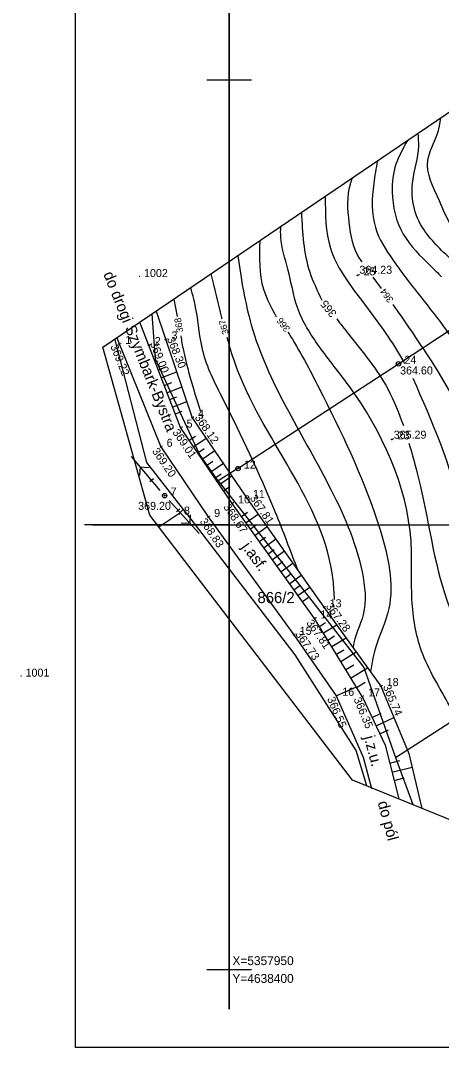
# Model space of a CAD drawing. Extents: x 4632591 to 4651936, y 5351032 to 5369988.
# Drawn here: x 4638376.6 to 4638423.8, y 5357941.2 to 5358056.7 of the extents above; entities that cross this region are included whole.
import ezdxf

# ---------------------------------------------------------------- set-up
doc = ezdxf.new("R2010")
doc.units = 0
for name, color, linetype in [('EBUPP_312', 7, 'Continuous'), ('EDZPD_211', 7, 'Continuous'), ('EDZPD_219', 7, 'Continuous'), ('EDZPP_202', 7, 'Continuous'), ('SDRPK_420', 7, 'Continuous'), ('SDRPK_432', 7, 'Continuous'), ('UEEPA_510', 7, 'Continuous'), ('UEETA_517', 7, 'Continuous'), ('Warstwa 25', 7, 'Continuous'), ('Warstwa 40', 7, 'Continuous'), ('Warstwa 60', 7, 'Continuous'), ('Warstwa 62', 7, 'Continuous'), ('WUKPS_403', 7, 'Continuous'), ('WUKPS_820', 7, 'Continuous'), ('WUKPS_824', 7, 'Continuous'), ('WWRPH_811', 7, 'Continuous'), ('WWRPH_812', 7, 'Continuous'), ('WWRPH_814', 7, 'Continuous')]:
    doc.layers.add(name, color=color, linetype=linetype)

msp = doc.modelspace()

# ---------------------------------------------------------------- linework, layer by layer
at = {"layer": 'EBUPP_312'}
msp.add_lwpolyline([(4638382.73, 5358114.56), (4638591.48, 5358114.56), (4638591.48, 5357941.24), (4638382.73, 5357941.24), (4638382.73, 5358114.56)], dxfattribs=at)
at = {"layer": 'EDZPD_219'}
for p, q in [((4638419.02, 5358018.09), (4638429.37, 5358024.9)), ((4638391.73, 5358018.61), (4638391.37, 5358023.66)), ((4638390.75, 5358007), (4638387.18, 5358020.8)), ((4638396.67, 5358007.92), (4638391.73, 5358018.61)), ((4638400.99, 5358006.31), (4638419.02, 5358018.09)), ((4638398.75, 5358004.93), (4638396.67, 5358007.92)), ((4638394.86, 5358001.71), (4638390.75, 5358007)), ((4638400.99, 5358006.31), (4638398.75, 5358004.93)), ((4638398.75, 5358004.93), (4638404.22, 5357997.93)), ((4638394.86, 5358001.71), (4638394.25, 5358001.14)), ((4638395.23, 5358001.26), (4638394.86, 5358001.71)), ((4638394.25, 5358001.14), (4638392.12, 5357999.73)), ((4638407.4, 5357985.38), (4638395.23, 5358001.26)), ((4638404.22, 5357997.93), (4638415.12, 5357983.94)), ((4638414.27, 5357974.64), (4638407.4, 5357985.38)), ((4638415.12, 5357983.94), (4638418.67, 5357973.84)), ((4638418.67, 5357973.84), (4638428.49, 5357980.16)), ((4638415.46, 5357970.64), (4638414.27, 5357974.64)), ((4638418.67, 5357973.84), (4638420.62, 5357968.54))]:
    msp.add_line(p, q, dxfattribs=at)
at = {"layer": 'EDZPP_202'}
for centre in [(4638419.02, 5358018.09), (4638400.99, 5358006.31)]:
    msp.add_circle(centre, 0.25, dxfattribs=at)
at = {"layer": 'SDRPK_420'}
msp.add_line((4638412.04, 5357980.77), (4638414.24, 5357981.75), dxfattribs=at)
for points in [[(4638414.94, 5357980.7), (4638409.59, 5357989.47), (4638400.34, 5358002.4), (4638394.55, 5358010.92), (4638389.98, 5358022.76)], [(4638387.39, 5358021), (4638392.31, 5358008.76), (4638397.65, 5358000.87), (4638407.26, 5357987.63), (4638412.04, 5357980.77)], [(4638412.04, 5357980.77), (4638415.06, 5357973.86), (4638416, 5357970.36)], [(4638414.94, 5357980.7), (4638417.53, 5357975.21), (4638419.05, 5357969.18)]]:
    msp.add_lwpolyline(points, dxfattribs=at)
at = {"layer": 'UEEPA_510'}
msp.add_circle((4638392.75, 5358003.27), 0.25, dxfattribs=at)
at = {"layer": 'UEETA_517'}
for p, q in [((4638392.27, 5358003.84), (4638389.04, 5358007.66)), ((4638390.01, 5358006.52), (4638389.92, 5358005.52)), ((4638390.01, 5358006.52), (4638391, 5358006.43)), ((4638391.49, 5358005.15), (4638391.11, 5358004.83)), ((4638393.26, 5358002.72), (4638396.63, 5357999.02)), ((4638394.08, 5358001.44), (4638394.45, 5358001.78)), ((4638395.61, 5358000.13), (4638395.66, 5358001.13)), ((4638395.61, 5358000.13), (4638394.62, 5358000.18))]:
    msp.add_line(p, q, dxfattribs=at)
at = {"layer": 'Warstwa 40'}
for p, q in [((4638385.83, 5358019.95), (4638506.88, 5358102.23)), ((4638391.08, 5358001.06), (4638385.83, 5358019.95)), ((4638413.84, 5357971.3), (4638391.08, 5358001.06)), ((4638432.85, 5357963.55), (4638413.84, 5357971.3))]:
    msp.add_line(p, q, dxfattribs=at)
at = {"layer": 'Warstwa 60'}
for p, q in [((4638400, 5358109.24), (4638400, 5358000)), ((4638400, 5358000), (4638400, 5358108.37)), ((4638397.5, 5358050), (4638400, 5358050)), ((4638400, 5358050), (4638402.5, 5358050)), ((4638400, 5358000), (4638383.76, 5358000)), ((4638384.64, 5358000), (4638400, 5358000)), ((4638400, 5357945.55), (4638400, 5358000)), ((4638400, 5358000), (4638400, 5357945.55)), ((4638400, 5358000), (4638516.95, 5358000)), ((4638397.5, 5357950), (4638400, 5357950)), ((4638400, 5357950), (4638402.5, 5357950))]:
    msp.add_line(p, q, dxfattribs=at)
at = {"layer": 'WUKPS_403'}
for centre in [(4638414.43, 5358028.03), (4638387.66, 5358020.32), (4638390.97, 5358020.19), (4638392.86, 5358020.83), (4638419.02, 5358018.09), (4638395.83, 5358012.03), (4638394.55, 5358010.92), (4638418.27, 5358009.59), (4638392.31, 5358008.76), (4638392.75, 5358003.27), (4638402, 5358003), (4638400.34, 5358002.4), (4638397.65, 5358000.87), (4638410.62, 5357990.72), (4638409.59, 5357989.47), (4638407.26, 5357987.63), (4638412.04, 5357980.77), (4638417.03, 5357981.86), (4638414.94, 5357980.7)]:
    msp.add_circle(centre, 0.045, dxfattribs=at)
at = {"layer": 'WUKPS_820'}
for p, q in [((4638392.05, 5358017.4), (4638392.92, 5358017.74)), ((4638394.1, 5358017.15), (4638392.4, 5358016.5)), ((4638392.72, 5358015.66), (4638393.55, 5358015.98)), ((4638394.67, 5358015.45), (4638393.04, 5358014.82)), ((4638393.34, 5358014.06), (4638394.14, 5358014.37)), ((4638395.22, 5358013.82), (4638393.66, 5358013.22)), ((4638393.96, 5358012.45), (4638394.72, 5358012.75)), ((4638395.52, 5358009.5), (4638396.21, 5358009.97)), ((4638397.42, 5358009.71), (4638396.02, 5358008.76)), ((4638396.48, 5358008.08), (4638397.18, 5358008.56)), ((4638398.38, 5358008.29), (4638396.98, 5358007.34)), ((4638397.45, 5358006.66), (4638398.15, 5358007.14)), ((4638399.35, 5358006.87), (4638397.95, 5358005.92)), ((4638398.41, 5358005.24), (4638399.11, 5358005.72)), ((4638400.32, 5358005.46), (4638398.91, 5358004.5)), ((4638399.38, 5358003.82), (4638400.08, 5358004.3)), ((4638401.39, 5358000.94), (4638402.08, 5358001.43)), ((4638403.28, 5358001.18), (4638401.91, 5358000.2)), ((4638402.39, 5357999.53), (4638403.07, 5358000.02)), ((4638404.27, 5357999.77), (4638402.91, 5357998.8)), ((4638403.39, 5357998.13), (4638404.07, 5357998.61)), ((4638405.26, 5357998.36), (4638403.92, 5357997.4)), ((4638404.4, 5357996.73), (4638405.07, 5357997.21)), ((4638406.21, 5357997.01), (4638404.88, 5357996.06)), ((4638405.36, 5357995.39), (4638406.02, 5357995.86)), ((4638407.15, 5357995.66), (4638405.84, 5357994.72)), ((4638406.32, 5357994.04), (4638406.97, 5357994.51)), ((4638408.1, 5357994.31), (4638406.8, 5357993.37)), ((4638407.28, 5357992.7), (4638407.93, 5357993.17)), ((4638409.05, 5357992.96), (4638407.76, 5357992.03)), ((4638408.24, 5357991.36), (4638408.88, 5357991.82)), ((4638410.14, 5357988.57), (4638410.84, 5357989.01)), ((4638412.08, 5357988.71), (4638410.61, 5357987.81)), ((4638411.07, 5357987.04), (4638411.84, 5357987.51)), ((4638413.14, 5357987.24), (4638411.54, 5357986.27)), ((4638412.05, 5357985.44), (4638412.88, 5357985.94)), ((4638414.28, 5357985.66), (4638412.56, 5357984.6)), ((4638413.1, 5357983.71), (4638414, 5357984.26)), ((4638415.56, 5357983.89), (4638413.69, 5357982.75)), ((4638414.32, 5357981.72), (4638415.29, 5357982.32)), ((4638416.06, 5357978.33), (4638417.08, 5357978.81)), ((4638416.51, 5357977.38), (4638418.51, 5357978.32)), ((4638416.92, 5357976.5), (4638417.91, 5357976.96)), ((4638418.04, 5357973.19), (4638419.18, 5357973.48)), ((4638418.29, 5357972.19), (4638420.56, 5357972.76)), ((4638418.53, 5357971.25), (4638419.65, 5357971.54))]:
    msp.add_line(p, q, dxfattribs=at)
at = {"layer": 'WUKPS_824'}
for points in [[(4638391.79, 5358024), (4638395.83, 5358012.03), (4638402, 5358003), (4638410.62, 5357990.72), (4638417.03, 5357981.86)], [(4638417.03, 5357981.86), (4638420.19, 5357974.3), (4638421.66, 5357968.11)]]:
    msp.add_lwpolyline(points, dxfattribs=at)
at = {"layer": 'WWRPH_811'}
for p, q in [((4638417.13, 5358026.55), (4638416.18, 5358027.83)), ((4638393.8, 5358025.37), (4638394.16, 5358023.4))]:
    msp.add_line(p, q, dxfattribs=at)
for points in [[(4638429.78, 5358029.1), (4638424.93, 5358033.66), (4638423.62, 5358036.41), (4638422.31, 5358040.97), (4638423.37, 5358043.85), (4638423.79, 5358045.75)], [(4638420.04, 5358043.2), (4638418.74, 5358040.53), (4638418.31, 5358037.41), (4638419.56, 5358032.66), (4638422.62, 5358029.09), (4638423.85, 5358027.88)], [(4638414.96, 5358029.5), (4638414.68, 5358029.9), (4638413.49, 5358033.97), (4638413.62, 5358038.28), (4638413.86, 5358039)], [(4638403.43, 5358031.91), (4638403.86, 5358026.47), (4638405.29, 5358023.38)], [(4638399.21, 5358023.11), (4638399.17, 5358023.28), (4638398, 5358028.22)], [(4638429.48, 5357998.93), (4638429.44, 5358001.08), (4638422.12, 5358019.34), (4638418.41, 5358024.77)], [(4638394.56, 5358021.23), (4638394.86, 5358019.59), (4638395.92, 5358015.52), (4638396.76, 5358012.77)], [(4638406.61, 5358021.64), (4638407.11, 5358020.84), (4638410.55, 5358014.46), (4638416.99, 5357999.33), (4638417.93, 5357990.58), (4638416.37, 5357985.89), (4638415.87, 5357983.47)], [(4638411.84, 5357991.59), (4638411.68, 5357993.76), (4638400.67, 5358018.15), (4638399.78, 5358021.03)]]:
    msp.add_spline(points, degree=3, dxfattribs=at)
at = {"layer": 'WWRPH_812'}
for points in [[(4638429.32, 5358024.94), (4638427.44, 5358027.34), (4638423.87, 5358030.84), (4638421.06, 5358034.72), (4638420.62, 5358038.6), (4638421.31, 5358042.54), (4638421.22, 5358044)], [(4638416.66, 5358040.9), (4638416.24, 5358038.35), (4638416.43, 5358033.41), (4638418.37, 5358029.78), (4638424, 5358022.4), (4638426.69, 5358017.96), (4638428.19, 5358012.08), (4638431.44, 5358002.21), (4638432.31, 5357998.45), (4638431.75, 5357994.2), (4638430.75, 5357990.45), (4638430.69, 5357987.76), (4638431.75, 5357984.32), (4638434.63, 5357979.63), (4638437.75, 5357976.69), (4638441.32, 5357974.51), (4638445.18, 5357971.85)], [(4638410.8, 5358036.92), (4638411.37, 5358031.09), (4638414.74, 5358025.4), (4638418.81, 5358019.65), (4638419.71, 5358018.14)], [(4638434.39, 5357964.59), (4638430.31, 5357968.13), (4638428.44, 5357971.44), (4638425, 5357979.2), (4638421.75, 5357985.45), (4638420.56, 5357991.2), (4638420.43, 5357998.14), (4638413.43, 5358015.65), (4638410.12, 5358020.03), (4638407.68, 5358024.4), (4638406.61, 5358028.72), (4638405.8, 5358032.34), (4638405.8, 5358033.52)], [(4638400.96, 5358030.23), (4638402.49, 5358022.46), (4638411.18, 5358004.46), (4638414.93, 5357994.7), (4638415.06, 5357989.89), (4638413.93, 5357986.26), (4638413.92, 5357986.16)], [(4638407.75, 5357994.8), (4638405.18, 5358001.45), (4638399.3, 5358014.15), (4638397.05, 5358019.53), (4638396.3, 5358024.09), (4638395.7, 5358026.66)], [(4638420.63, 5358016.49), (4638426, 5358001.45), (4638426.69, 5357995.14), (4638426.75, 5357992.2), (4638427.81, 5357987.64), (4638428.94, 5357984.51), (4638430.12, 5357982.2), (4638431.5, 5357980.13), (4638433.25, 5357977.88), (4638438.5, 5357973.88), (4638440.69, 5357972.38), (4638442.82, 5357970.75), (4638443.16, 5357970.49)]]:
    msp.add_spline(points, degree=3, dxfattribs=at)
at = {"layer": 'WWRPH_814'}
for points in [[(4638408.12, 5358035.1), (4638409.05, 5358028.4), (4638410.43, 5358025.24)], [(4638412.08, 5358023.15), (4638413.43, 5358021.4), (4638417.81, 5358015.27), (4638419.58, 5358011.16)], [(4638420.19, 5358009.17), (4638421.25, 5358005.33), (4638424.5, 5357991.39), (4638428.75, 5357982.57), (4638429.93, 5357980.49)]]:
    msp.add_spline(points, degree=3, dxfattribs=at)

# ---------------------------------------------------------------- texts
at = {"layer": 'EDZPD_211'}
msp.add_text('866/2', height=1.25, dxfattribs=at).set_placement((4638403.18, 5357991.19))
at = {"layer": 'SDRPK_432'}
for s, rotation, p in [('do drogi Szymbark-Bystra', 291.9124, (4638385.84, 5358028.18)), ('j.asf.', 305.9733, (4638401.36, 5357997.51)), ('j.z.u.', 284.9951, (4638415.12, 5357976.12)), ('do pól', 284.9951, (4638416.67, 5357968.78))]:
    msp.add_text(s, height=1.25, rotation=rotation, dxfattribs=at).set_placement(p)
at = {"layer": 'Warstwa 25'}
for s, p in [(' X=5357950 ', (4638400, 5357950.5)), (' Y=4638400 ', (4638400, 5357948.5))]:
    msp.add_text(s, height=1, dxfattribs=at).set_placement(p)
at = {"layer": 'Warstwa 62'}
for s, p in [('. 1002', (4638389.77, 5358027.84)), ('. 1002', (4638389.77, 5358027.84)), ('. 1002', (4638389.77, 5358027.84)), ('. 1002', (4638389.77, 5358027.84)), ('. 25', (4638414.43, 5358028.03)), ('. 1', (4638387.66, 5358020.32)), ('. 3', (4638392.86, 5358020.83)), ('. 2', (4638390.97, 5358020.19)), ('. 24', (4638419.02, 5358018.09)), ('. 4', (4638395.83, 5358012.03)), ('. 5', (4638394.55, 5358010.92)), ('. 6', (4638392.31, 5358008.76)), ('. 23', (4638418.27, 5358009.59)), ('. 12', (4638400.99, 5358006.31)), ('. 7', (4638392.75, 5358003.27)), ('. 11', (4638402, 5358003)), ('. 10', (4638400.34, 5358002.4)), ('. 8', (4638394.25, 5358001.14)), ('. 9', (4638397.65, 5358000.87)), ('. 13', (4638410.62, 5357990.72)), ('. 14', (4638409.59, 5357989.47)), ('. 15', (4638407.26, 5357987.63)), ('. 1001', (4638376.46, 5357982.92)), ('. 1001', (4638376.46, 5357982.92)), ('. 18', (4638417.03, 5357981.86)), ('. 16', (4638412.04, 5357980.77)), ('. 17', (4638414.94, 5357980.7))]:
    msp.add_text(s, height=0.9, dxfattribs=at).set_placement(p)
at = {"layer": 'WUKPS_403'}
for s, p in [('364.23', (4638414.63, 5358028.21)), ('364.60', (4638419.2, 5358016.89)), ('365.29', (4638418.48, 5358009.67)), ('369.20', (4638389.78, 5358001.67))]:
    msp.add_text(s, height=0.9, dxfattribs=at).set_placement(p)
for s, rotation, p in [('369.22', 291.9124, (4638386.64, 5358020.06)), ('369.00', 291.9124, (4638391.09, 5358020.38)), ('368.30', 291.9124, (4638393, 5358020.9)), ('368.12', 304.3439, (4638396.09, 5358012.05)), ('369.01', 304.3439, (4638393.59, 5358010.38)), ('369.20', 304.3439, (4638391.3, 5358008.27)), ('367.81', 304.3439, (4638402.28, 5358002.99)), ('368.67', 304.3439, (4638399.31, 5358001.99)), ('368.83', 304.3439, (4638396.66, 5358000.36)), ('367.28', 305.8848, (4638410.82, 5357990.83)), ('367.81', 304.8685, (4638408.63, 5357988.96)), ('367.73', 304.8685, (4638407.39, 5357987.69)), ('365.74', 292.6941, (4638417.26, 5357981.81)), ('366.55', 292.6941, (4638410.99, 5357980.44)), ('366.35', 292.6941, (4638413.96, 5357980.39))]:
    msp.add_text(s, height=0.9, rotation=rotation, dxfattribs=at).set_placement(p)
at = {"layer": 'WWRPH_811'}
for s, rotation, p in [('364', 125.9747, (4638418.5, 5358025.3)), ('368', 100.3487, (4638394.86, 5358021.67)), ('367', 105.3196, (4638399.99, 5358021.5)), ('366', 127.7997, (4638406.9, 5358022.04))]:
    msp.add_text(s, height=0.75, rotation=rotation, dxfattribs=at).set_placement(p)
at = {"layer": 'WWRPH_814'}
msp.add_text('365', height=0.9, rotation=128.7519, dxfattribs=at).set_placement((4638412.14, 5358023.77))

doc.saveas('drawing.dxf')
